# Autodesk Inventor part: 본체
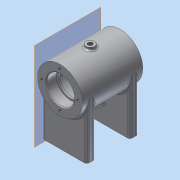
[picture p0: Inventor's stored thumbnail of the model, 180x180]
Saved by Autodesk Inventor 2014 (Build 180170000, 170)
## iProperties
Created: 2020-07
Part Number: 본체
Material: Aluminum 6061
Document SubType Name: Modeling
Designer: kh
Density: 2.71 g/cm^3
Appearance: Aluminum - Flat
Mass: 306.379 g
Surface Area: 357.564 cm^2
Volume: 113.055 cm^3
Author: kh
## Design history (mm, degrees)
sketch "Sketch1"
  geometry: C1 r 26 at (0, 0); 1 further point
  constraints: 1 centre point, 1 coincident
  dimensions: "d0" = 26 radius of C1
extrude "Extrusion1" new body sketch "Sketch1" stored distance "d1" = 70; taper "d2" = 0 deg
workplane "Work Plane1"
sketch "Sketch2"
  geometry: L1 (26, 0)-(26, -64); L2 (26, -64)-(-26, -64); L3 (-26, -64)-(-26, 0); A1 r 26 centre (0, 0) between (26, 0) and (-26, 0) reference; 1 further point
  constraints: 6 end point, 2 point on circle, 2 tangent, 1 perpendicular, 1 vertical
  dimensions: "d4" = 64 distance of L1.start L1.end; "d5" = 52 distance of L1.end L2.end
extrude "Extrusion2" join sketch "Sketch2" distance "d6" = 10; taper "d7" = 0 deg
mirror "Mirror1"
sketch "Sketch3"
  geometry: L1 (26, -35)-(26, 35) reference; L2 (0, 20)-(-64, 20) reference; L3 (0, -20)-(-64, -20) reference; L4 (0, -20)-(-64, -20) reference; L5 (0, -30)-(0, -20) reference; L6 (0, -30)-(-64, -30) reference; L7 (-64, -20)-(-64, -30) reference; L8 (0, 20)-(-64, 20) reference; L9 (-64, 20)-(-64, 30) reference; L10 (0, 30)-(-64, 30) reference; L11 (0, 20)-(0, 30) reference; L12 (0, -30)-(0, -20) reference; L13 (0, -20)-(0, -20) reference; L14 (0, -30)-(0, -20) reference; L15 (0, -30)-(0, -30) reference; L16 (0, 20)-(0, 30) reference; L17 (0, 30)-(0, 30) reference; L18 (0, 20)-(0, 30) reference; L19 (0, 20)-(0, 20) reference; L20 (-26, -35)-(26, -35) reference; L21 (26, 35)-(-26, 35) reference; L22 (-64, 20)-(-64, 30) reference; L23 (0, 35)-(0, -35); L24 (0, 35)-(16, 35); L25 (16, 35)-(16, 23); L26 (16, 23)-(14, 23); L27 (14, 23)-(14, 21); L28 (14, 21)-(21, 21); L29 (21, 21)-(21, -21); L30 (21, -21)-(14, -21); L31 (14, -21)-(14, -23); L32 (14, -23)-(16, -23); L33 (16, -23)-(16, -35); L34 (16, -35)-(0, -35); 1 further point
  constraints: 24 end point, 6 parallel, 3 perpendicular, 2 midpoint, 2 point on line, 1 collinear
  dimensions: "d8" = 12 distance of L25.end L24.end; "d9" = 12 distance of L33.end L32.end; "d10" = 2 distance of L27.end L26.end; "d11" = 42 distance of L29.end L28.end; "d12" = 42 diameter of L29 L23; "d13" = 28 diameter of L31 L23; "d14" = 28 diameter of L27 L23; "d15" = 32 diameter of L25 L23; "d16" = 32 diameter of L33 L23
revolve "Revolution1" sketch "Sketch3" stored, may be unused: angle "d17" = 90 deg
sketch "Sketch4"
  geometry: L1 (26, -64)-(26, 0) reference; L2 (-26, 0)-(-26, -64) reference; L3 (-26, -64)-(26, -64) reference; L4 (26, -64)-(26, 0) reference; L5 (0, 0)-(0, -26); L6 (8.241, -22.643)-(10, -27.475); L7 (15.638, -25.423)-(13.88, -20.591); L8 (10, -27.475)-(15.638, -25.423); L9 (8.241, -22.643)-(13.88, -20.591); L10 (0, 0)-(8.241, -22.643); A1 r 26 centre (0, 0) between (-26, 0) and (26, 0) reference; A2 r 26 centre (0, 0) between (-26, 0) and (26, 0) reference; 1 further point
  constraints: 12 end point, 3 perpendicular, 1 point on circle
  dimensions: "d21" = 6 distance between parallel lines of L7 L6; "d89" = 20 deg angle of L6 L5
revolve "Revolution2" sketch "Sketch4" stored, may be unused: angle "d22" = 90 deg
workplane "Work Plane2"
sketch "Sketch5"
  geometry: C1 r 5 at (0, 0); 1 further point
  constraints: 1 centre point, 1 coincident
  dimensions: "d24" = 5 radius of C1
extrude "Extrusion3" join sketch "Sketch5" distance "d25" = 6.25; taper "d26" = 0 deg
sketch "Sketch6"
  geometry: L1 (0, -10)-(52, -10) reference; L2 (52, 0)-(52, -10) reference; L3 (26, 20)-(26, -15.02); 2 further points
  constraints: 2 end point, 1 parallel
  dimensions: "d27" = 20 distance from line of L3 point (6, -5); "d28" = 20 distance from line of L3 point (46, -5); "d29" = 5 distance from line of point (46, -5) L1; "d30" = 5 distance from line of point (6, -5) L1
hole "Hole1" sketch "Sketch6" at (46, -5), (6, -5) diameter "d31" = 4.134; stored, may be unused: countersink angle "d35" = 90 deg, drill point angle "d37" = 118 deg; dims "d32" = 8, "d33" = 4, "d34" = 2, "d36" = 10
mirror "Mirror2"
hole "Hole2" diameter "d40" = 5.188; stored, may be unused: countersink angle "d44" = 90 deg, drill point angle "d46" = 118 deg; dims "d38" = 10, "d39" = 10, "d41" = 8, "d42" = 4, "d43" = 2, "d45" = 16.25
hole "Hole3" diameter "d49" = 5.188; stored, may be unused: countersink angle "d53" = 90 deg, drill point angle "d55" = 118 deg; dims "d50" = 6, "d51" = 4, "d52" = 2, "d54" = 16.25, "d81" = 10, "d82" = 10
sketch "Sketch7" dims "d56" = 21
  geometry: C1 r 26 at (0, 0) reference; 2 further points
  constraints: 1 coincident, 1 horizontal alignment, 2 other
hole "Hole4" sketch "Sketch7" at (-21, 0) diameter "d57" = 3.242; stored, may be unused: countersink angle "d61" = 90 deg, drill point angle "d63" = 118 deg; dims "d58" = 8, "d59" = 4, "d60" = 2, "d62" = 10
pattern_circular "Circular Pattern1" dims angle "d65" = 360 deg
mirror "Mirror3"
workplane "Work Plane3"
fillet "Fillet1" dims "d72" = 2
chamfer "Chamfer1" distance "d73" = 1; stored, may be unused: second distance "d74" = 2, angle "d75" = 45 deg
fillet "Fillet3" dims "d77" = 3
fillet "Fillet4" dims "d78" = 3
fillet "Fillet5" dims "d79" = 0.3
fillet "Fillet6" dims "d80" = 3
workplane "Work Plane5"
sketch "Sketch11"
  geometry: L1 (-26, -35)-(-26, 35) reference; L2 (16, -34)-(-16, -34) reference; L3 (-26, -35)-(26, -35) reference; 2 further points
  constraints: 1 other
  dimensions: "d91" = 35 distance from line of point (0, 0) L3; "d92" = 26 distance from line of point (0, 0) L1
emboss "Emboss3" sketch "Sketch11" dims "d93" = 0.5, "d94" = 0
body "Solid1"
node "Projected Loop1"
node "Projected Loop2"
node "Projected Loop3"
node "Projected Loop4"
other parameters: "d23" = 29, "d67" = 26, "d90" = -26
